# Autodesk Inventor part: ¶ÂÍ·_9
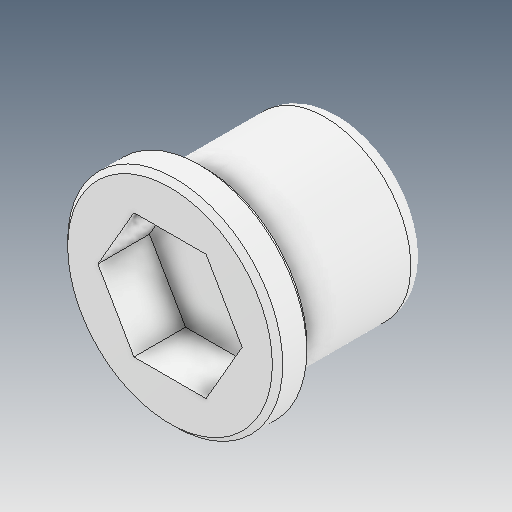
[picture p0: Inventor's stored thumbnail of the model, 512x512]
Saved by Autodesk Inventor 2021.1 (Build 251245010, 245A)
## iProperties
Created: 2021-06
Part Number: ¶ÂÍ·_9
Material: Ogólny
Document SubType Name: Modeling
Designer: user
Density: 1 g/cm^3
Appearance: Domyślna
Author: user
Revision Number: ÈÎºÎ
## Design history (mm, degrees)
feature "ÊäÈë1"
node "Bryła1"
